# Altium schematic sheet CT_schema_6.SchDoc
size 581 x 363 mm
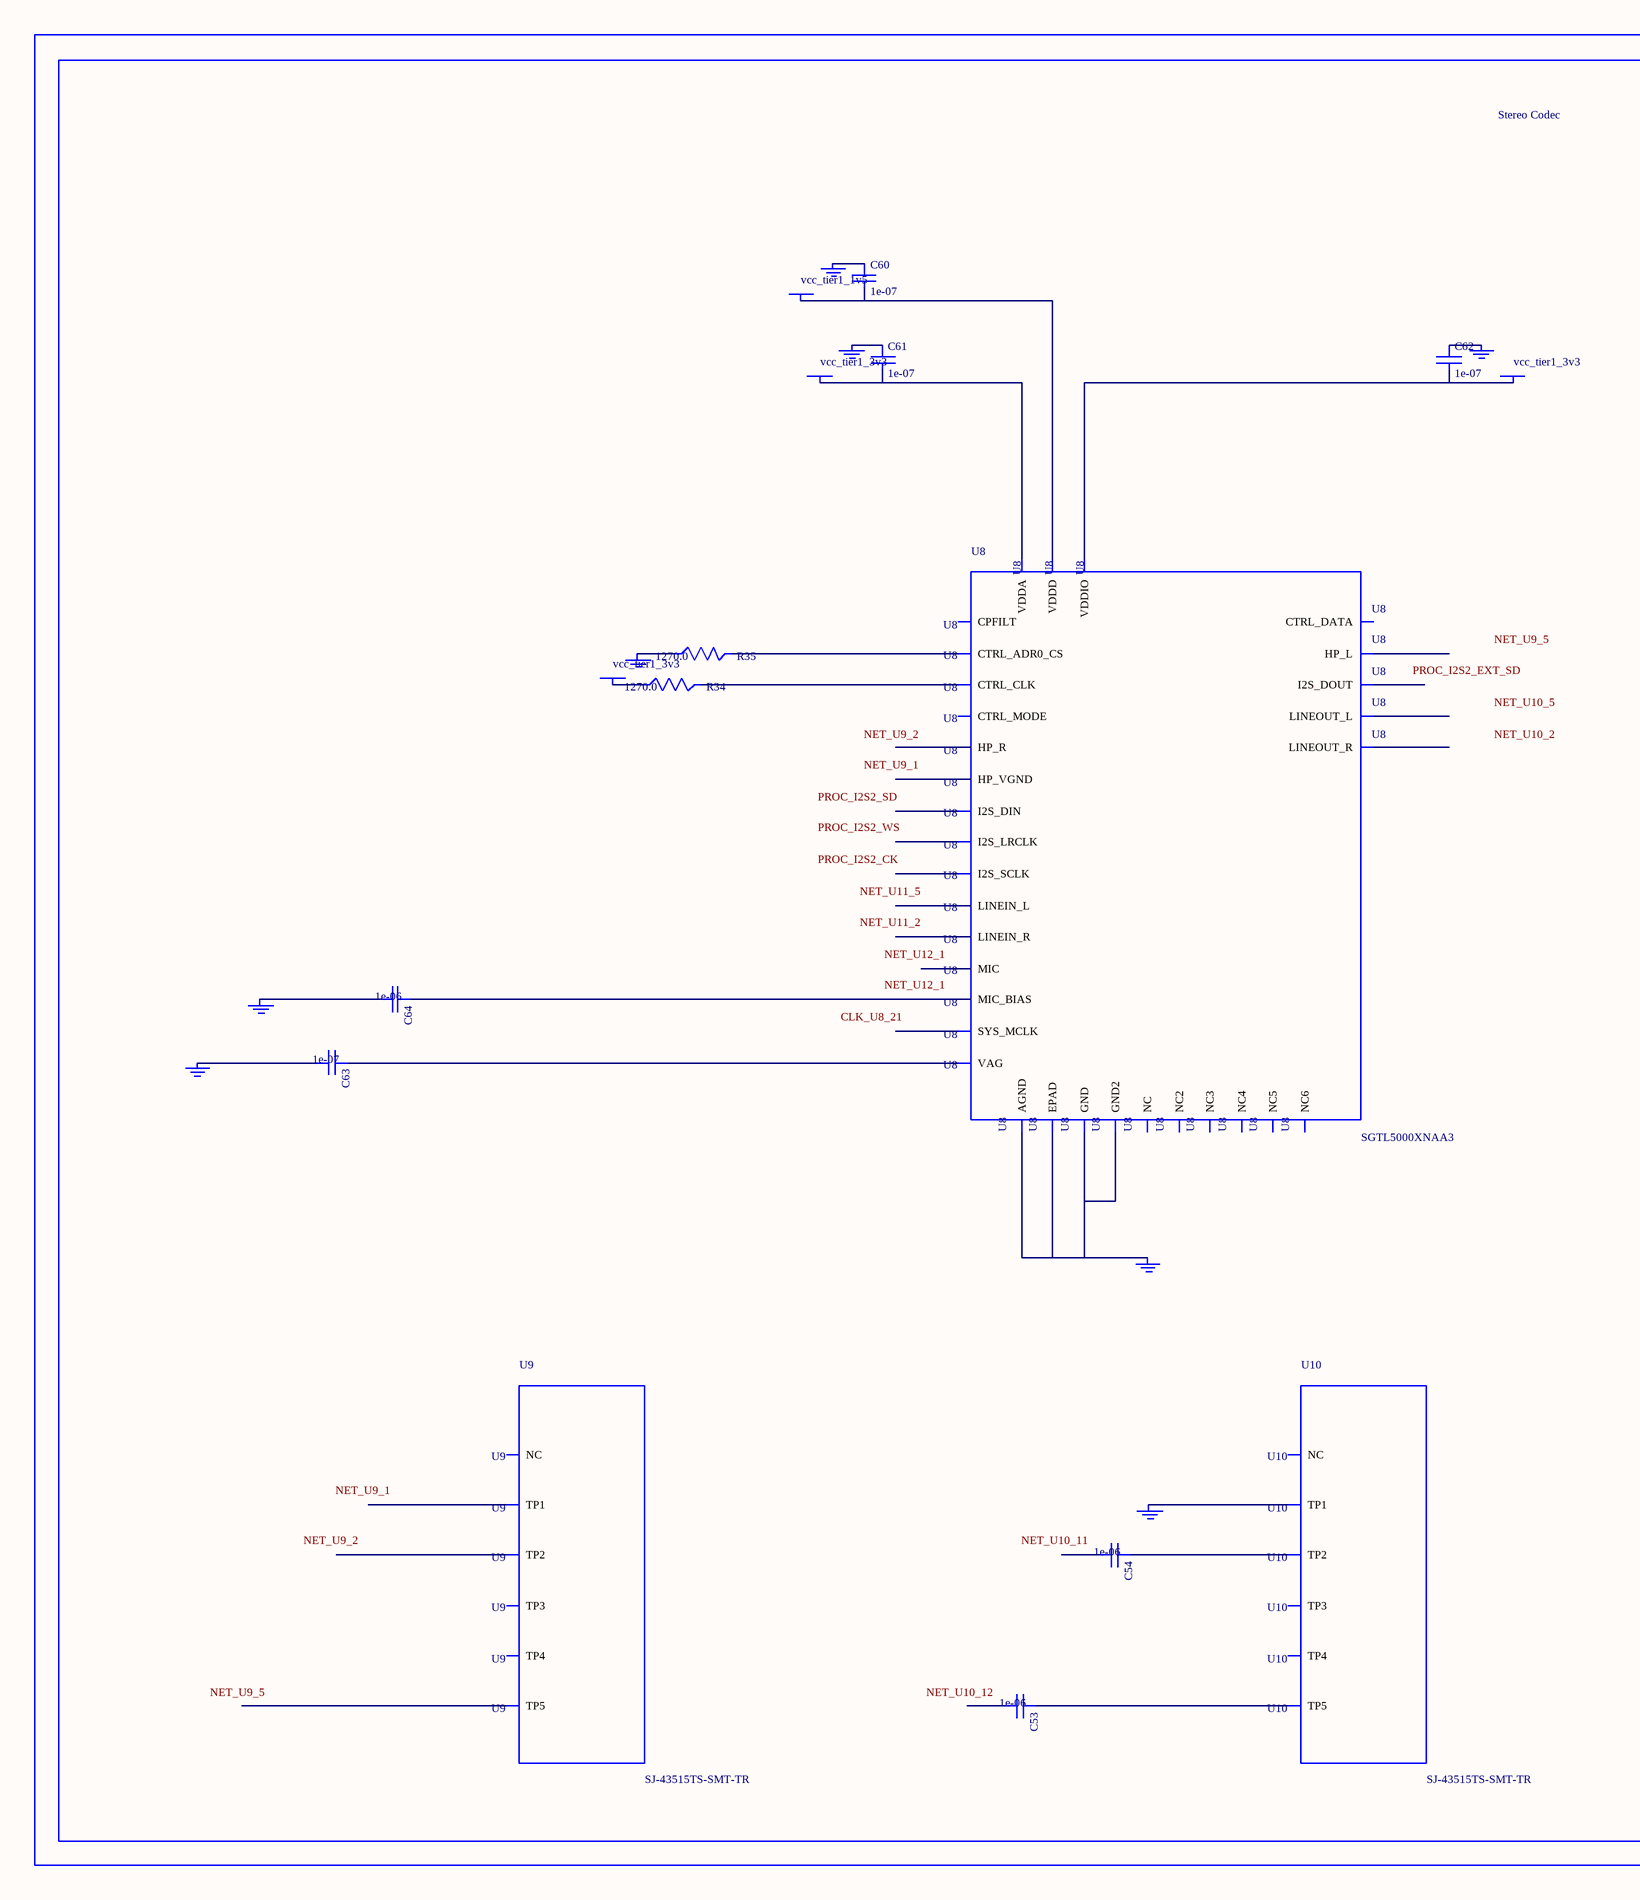
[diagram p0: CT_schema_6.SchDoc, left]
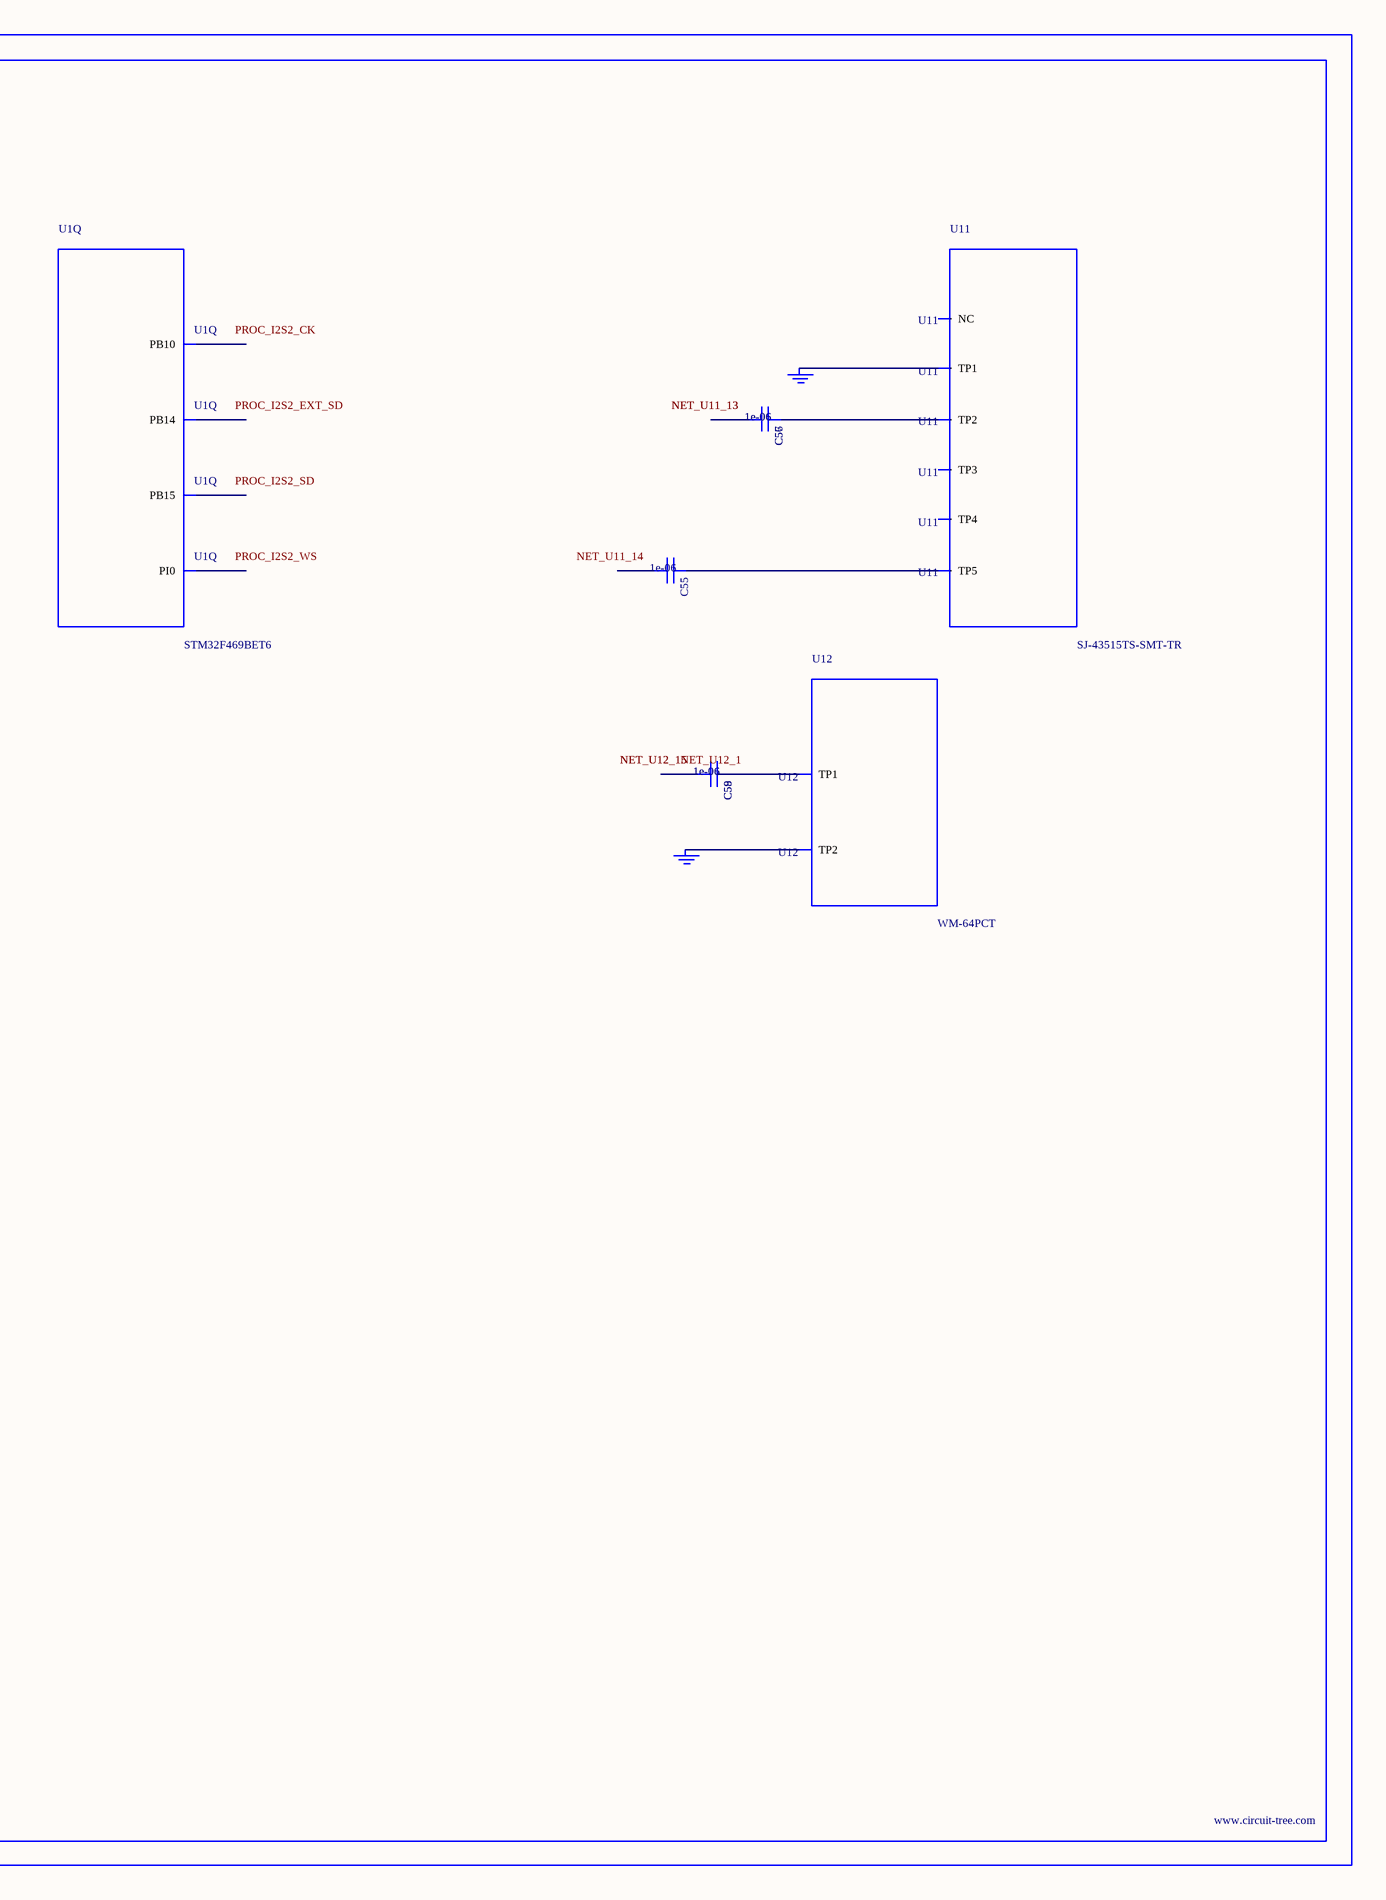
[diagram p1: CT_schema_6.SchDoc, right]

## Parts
BORDER5  (no value)
C53  1e-06  [C0603]
C54  1e-06  [C0603]
C55  1e-06  [C0603]
C56  1e-06  [C0603]
C57  1e-06  [C0603]
C58  1e-06  [C0603]
C59  1e-06  [C0603]
C60  1e-07  [C0402]
C61  1e-07  [C0402]
C62  1e-07  [C0402]
C63  1e-07  [C0402]
C64  1e-06  [C0603]
GND_INSTANCE_5_0  (no value)
GND_INSTANCE_5_1  (no value)
GND_INSTANCE_5_2  (no value)
GND_INSTANCE_5_3  (no value)
GND_INSTANCE_5_4  (no value)
GND_INSTANCE_5_5  (no value)
GND_INSTANCE_5_6  (no value)
GND_INSTANCE_5_7  (no value)
GND_INSTANCE_5_8  (no value)
GND_INSTANCE_5_9  (no value)
GND_INSTANCE_5_10  (no value)
POWER_INSTANCE_5_0  vcc_tier1_3v3
POWER_INSTANCE_5_1  vcc_tier1_3v3
POWER_INSTANCE_5_2  vcc_tier1_3v3
POWER_INSTANCE_5_3  vcc_tier1_1v5
R34  1270.0  [R0603]
R35  1270.0  [R0603]
U1  STM32F469BET6  [LQFP208]  (part Q of 18)
U8  SGTL5000XNAA3  [QFN-32]
U9  SJ-43515TS-SMT-TR  [SJ-43515TS-SMT-TR]
U10  SJ-43515TS-SMT-TR  [SJ-43515TS-SMT-TR]
U11  SJ-43515TS-SMT-TR  [SJ-43515TS-SMT-TR]
U12  WM-64PCT  [WM-64PC]

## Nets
NetC53_1: C53.1 U10.5(TP5)
NetC54_1: C54.1 U10.2(TP2)
NetC55_1: C55.1 U11.5(TP5)
NetC56_1: C56.1 C57.1 U11.2(TP2)
NetC56_2: C56.2 C57.2
NetC58_1: C58.1 C59.1 U12.1(TP1)
NetC58_2: C58.2 C59.2
NetC60_1: C60.1 GND_INSTANCE_5_5.0(GND)
NetC60_2: C60.2 POWER_INSTANCE_5_3.0(PWR) U8.30(VDDD)
NetC61_1: C61.1 GND_INSTANCE_5_1.0(GND)
NetC61_2: C61.2 POWER_INSTANCE_5_0.0(PWR) U8.5(VDDA)
NetC62_1: C62.1 GND_INSTANCE_5_4.0(GND)
NetC62_2: C62.2 POWER_INSTANCE_5_1.0(PWR) U8.20(VDDIO)
NetC63_1: C63.1 U8.10(VAG)
NetC63_2: C63.2 GND_INSTANCE_5_2.0(GND)
NetC64_1: C64.1 U8.16(MIC_BIAS)
NetC64_2: C64.2 GND_INSTANCE_5_3.0(GND)
NetGND_INSTANCE_5_0_0: GND_INSTANCE_5_0.0(GND) U8.1(GND) U8.3(GND2) U8.7(AGND) U8.EXP(EPAD)
NetGND_INSTANCE_5_6_0: GND_INSTANCE_5_6.0(GND) R35.1
NetGND_INSTANCE_5_7_0: GND_INSTANCE_5_7.0(GND) U10.1(TP1)
NetGND_INSTANCE_5_8_0: GND_INSTANCE_5_8.0(GND) GND_INSTANCE_5_9.0(GND) U11.1(TP1)
NetGND_INSTANCE_5_10_0: GND_INSTANCE_5_10.0(GND) U12.2(TP2)
NetPOWER_INSTANCE_5_2_0: POWER_INSTANCE_5_2.0(PWR) R34.1
NetR34_2: R34.2 U8.29(CTRL_CLK)
NetR35_2: R35.2 U8.31(CTRL_ADR0_CS)

Not connected (* = marked no-connect by the designer): C53 2; C54 2; C55 2; U1 90(PB10) 106(PB14) 107(PB15) 154(PI0); U8 2(HP_R) 4(HP_VGND) 6(HP_L) 8(NC) 9(NC2) 11(LINEOUT_R) 12(LINEOUT_L) 13(LINEIN_R) 14(LINEIN_L) 15(MIC) 17(NC3) 18(CPFILT) 19(NC4) 21(SYS_MCLK) 22(NC5) 23(I2S_LRCLK) 24(I2S_SCLK) 25(I2S_DOUT) 26(I2S_DIN) 27(CTRL_DATA) 28(NC6) 32(CTRL_MODE); U9 1(TP1) 2(TP2) 3(TP3) 4(TP4) 5(TP5) 6(NC); U10 3(TP3) 4(TP4) 6(NC); U11 3(TP3) 4(TP4) 6(NC)

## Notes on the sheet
- Labels drawn without touching a wire or pin: CLK_U8_21, NET_U9_1, NET_U9_2, NET_U9_5, NET_U10_2, NET_U10_5, NET_U10_11, NET_U10_12, NET_U11_2, NET_U11_5, NET_U11_14, NET_U12_1, PROC_I2S2_CK, PROC_I2S2_EXT_SD, PROC_I2S2_SD, PROC_I2S2_WS

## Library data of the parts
BORDER5 = BORDER_PAGE5
C53-C59 C64 = C0603C105K3RACTU
C60-C63 = C0402C104K3RACTU
GND_INSTANCE_5_0-GND_INSTANCE_5_10 = GND
POWER_INSTANCE_5_0-POWER_INSTANCE_5_3 = PWR
R34 R35 = RC0603FR-071K27L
